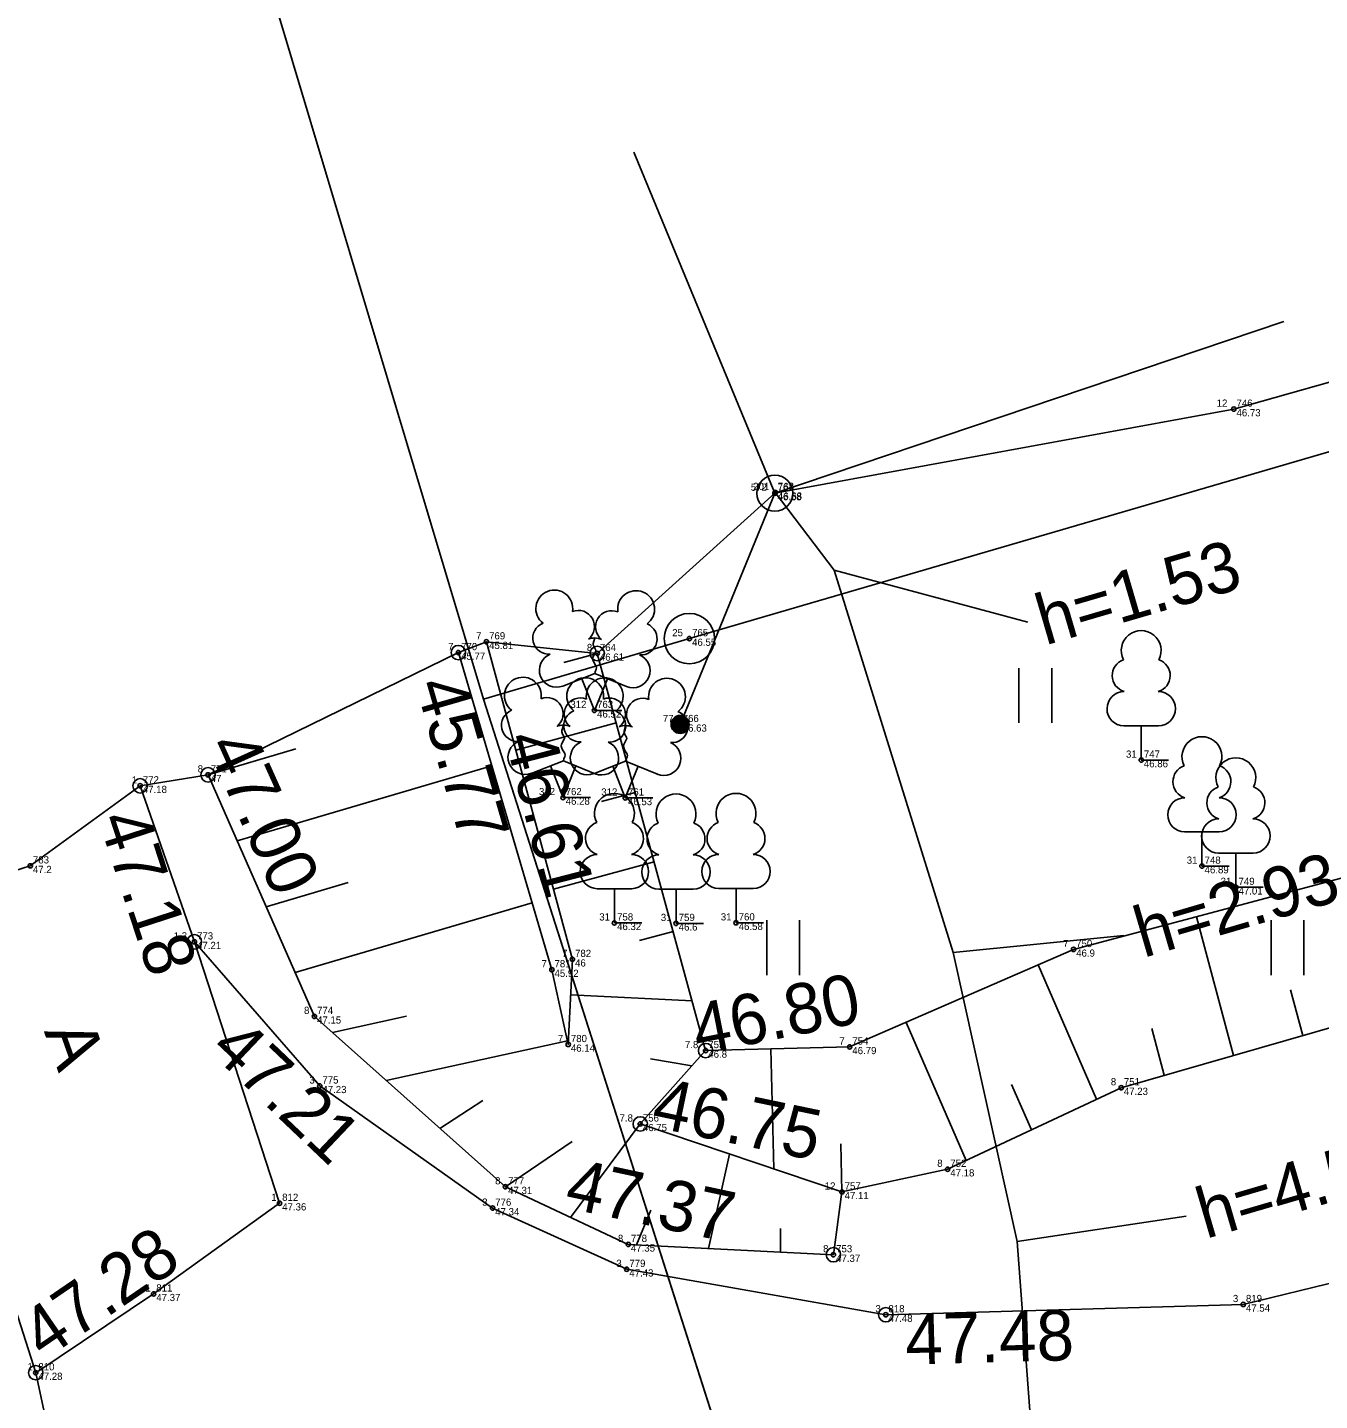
# Model space of a CAD drawing. Extents: x 543497 to 552146, y 6567125 to 6579845.
# Drawn here: x 545912.51 to 545930.45, y 6577662.71 to 6577681.77 of the extents above; entities that cross this region are included whole.
import ezdxf

# ---------------------------------------------------------------- set-up
doc = ezdxf.new("R2010")
doc.units = 0
for name, color, linetype in [('xref_Kangru tee 1_geodeesia$0$ABIJOONIS', 7, 'Continuous'), ('xref_Kangru tee 1_geodeesia$0$HALJASTUS', 7, 'Continuous'), ('xref_Kangru tee 1_geodeesia$0$korgus-EH2000', 7, 'Continuous'), ('xref_Kangru tee 1_geodeesia$0$mootkood', 7, 'Continuous'), ('xref_Kangru tee 1_geodeesia$0$MOOTKORG-eh2000', 7, 'Continuous'), ('xref_Kangru tee 1_geodeesia$0$mootmpunkt', 7, 'Continuous'), ('xref_Kangru tee 1_geodeesia$0$MOOTNR', 7, 'Continuous'), ('xref_Kangru tee 1_geodeesia$0$MOOTPIIR', 7, 'Continuous'), ('xref_Kangru tee 1_geodeesia$0$MPKAABEL', 7, 'Continuous'), ('xref_Kangru tee 1_geodeesia$0$MPOHULIIN', 7, 'Continuous'), ('xref_Kangru tee 1_geodeesia$0$PIIR', 7, 'Continuous'), ('xref_Kangru tee 1_geodeesia$0$PIIRIMLEITUD', 7, 'Continuous'), ('xref_Kangru tee 1_geodeesia$0$Post', 7, 'Continuous'), ('xref_Kangru tee 1_geodeesia$0$PUU', 7, 'Continuous'), ('xref_Kangru tee 1_geodeesia$0$RELJEEF', 7, 'Continuous'), ('xref_Kangru tee 1_geodeesia$0$TEE', 7, 'Continuous')]:
    doc.layers.add(name, color=color, linetype=linetype)

# ---------------------------------------------------------------- blocks, each defined once
blk = doc.blocks.new('xref_Kangru tee 1_geodeesia$0$LEHTP1')
for p, q in [((0.48, 0.95), (-0.48, 0.95)), ((0, 0), (0, 0.95)), ((0.76, 0), (0, 0))]:
    blk.add_line(p, q)
for centre, radius, start, end in [((0, 3.04), 0.554, 332.5799, 207.4201), ((-0.34, 2.345), 0.465, 109.0217, 253.1415), ((0.34, 2.345), 0.465, 286.8508, 70.9859), ((-0.475, 1.425), 0.475, 90.0016, 269.3953), ((0.475, 1.425), 0.475, 270.6047, 89.9984)]:
    blk.add_arc(centre, radius, start, end)
blk = doc.blocks.new('xref_Kangru tee 1_geodeesia$0$LEHTP2')
for p, q in [((-0.88, 0.67), (0.01, 1.02)), ((0, 0), (-0.35, 0.88)), ((0, 0), (0.36, 0.88)), ((0.01, 1.02), (0.89, 0.66)), ((0.76, 0), (0, 0))]:
    blk.add_line(p, q)
blk.add_lwpolyline([(0.01, 2.01), (-0.03, 1.86), (-0.03, 1.82), (-0.01, 1.76), (0.03, 1.69), (0.04, 1.65), (0.01, 1.58), (-0.04, 1.48), (-0.05, 1.43), (-0.04, 1.4), (-0.02, 1.34), (0.05, 1.22), (0.06, 1.18), (0.05, 1.14), (0.02, 1.07), (0.01, 1.02)])
for centre, radius, start, end in [((-1.114, 2.828), 0.512, 111.5027, 232.5173), ((-1.114, 2.828), 0.512, 350.4856, 111.5002), ((1.158, 2.811), 0.512, 67.6168, 188.6314), ((1.158, 2.811), 0.512, 306.5997, 67.6143), ((-0.445, 2.327), 0.448, 308.5041, 111.5725), ((0.481, 2.318), 0.45, 67.7016, 230.5126), ((-1.262, 2.005), 0.448, 111.4304, 274.4987), ((1.293, 1.986), 0.448, 264.6183, 67.6866), ((0.008, 1.535), 0.475, 66.7655, 111.5015), ((-1.053, 1.117), 0.475, 111.5014, 291.5004), ((1.07, 1.101), 0.475, 247.6166, 67.6155)]:
    blk.add_arc(centre, radius, start, end)
blk = doc.blocks.new('xref_Kangru tee 1_geodeesia$0$PMTORU')
blk.add_circle((0, 0), 0.7)
blk = doc.blocks.new('xref_Kangru tee 1_geodeesia$0$PUPOST')
blk.add_circle((0, 0), 0.5)
blk = doc.blocks.new('xref_Kangru tee 1_geodeesia$0$hein')
for p, q in [((-0.455, 0.761), (-0.455, -0.761)), ((0.455, 0.761), (0.455, -0.761))]:
    blk.add_line(p, q)
blk = doc.blocks.new('xref_Kangru tee 1_geodeesia$0$ANKURP')
for radius in [0.25, 0.234, 0.219, 0.203, 0.188, 0.172, 0.156, 0.141, 0.125, 0.11, 0.0939, 0.0783, 0.0628, 0.0472, 0.0316, 0.016, 0.000371]:
    blk.add_circle((0, 0), radius)

msp = doc.modelspace()

# ---------------------------------------------------------------- linework, layer by layer
at = {"layer": 'xref_Kangru tee 1_geodeesia$0$ABIJOONIS'}
for p, q in [((545923.709, 6577674.241), (545926.396, 6577673.517)), ((545925.358, 6577668.93), (545927.728, 6577669.17)), ((545926.248, 6577664.92), (545928.595, 6577665.27))]:
    msp.add_line(p, q, dxfattribs=at)
at = {"layer": 'xref_Kangru tee 1_geodeesia$0$korgus-EH2000'}
for centre in [(545918.49, 6577673.095), (545920.417, 6577673.083), (545914.071, 6577671.246), (545915.014, 6577671.398), (545914.824, 6577669.08), (545921.922, 6577667.571), (545921.014, 6577666.552), (545923.697, 6577664.737), (545924.424, 6577663.904), (545912.621, 6577663.099)]:
    msp.add_circle(centre, 0.1, dxfattribs=at)
at = {"layer": 'xref_Kangru tee 1_geodeesia$0$mootmpunkt'}
for centre in [(545929.256, 6577676.475), (545922.889, 6577675.319), (545922.884, 6577675.308), (545918.879, 6577673.245), (545921.697, 6577673.289), (545918.49, 6577673.095), (545920.417, 6577673.083), (545920.378, 6577672.293), (545921.567, 6577672.098), (545927.97, 6577671.603), (545915.014, 6577671.398), (545914.071, 6577671.246), (545919.942, 6577671.083), (545920.807, 6577671.077), (545912.545, 6577670.135), (545928.813, 6577670.131), (545929.284, 6577669.837), (545920.656, 6577669.343), (545921.511, 6577669.336), (545922.344, 6577669.344), (545914.824, 6577669.08), (545920.072, 6577668.837), (545927.03, 6577668.974), (545919.787, 6577668.693), (545916.49, 6577668.045), (545920.014, 6577667.655), (545921.922, 6577667.571), (545923.922, 6577667.621), (545916.564, 6577667.08), (545927.692, 6577667.055), (545921.014, 6577666.552), (545925.282, 6577665.923), (545919.143, 6577665.68), (545923.815, 6577665.608), (545916.006, 6577665.451), (545918.964, 6577665.384), (545920.848, 6577664.88), (545923.697, 6577664.737), (545920.826, 6577664.534), (545914.258, 6577664.193), (545924.424, 6577663.904), (545929.387, 6577664.046), (545912.621, 6577663.099)]:
    msp.add_circle(centre, 0.03, dxfattribs=at)
at = {"layer": 'xref_Kangru tee 1_geodeesia$0$MOOTPIIR'}
msp.add_lwpolyline([(545946.849, 6577681.441), (545929.256, 6577676.475), (545922.884, 6577675.308), (545920.417, 6577673.083), (545918.879, 6577673.245), (545918.49, 6577673.095), (545915.014, 6577671.398), (545914.071, 6577671.246), (545912.545, 6577670.135), (545910.571, 6577669.508), (545908.59, 6577668.894), (545905.466, 6577667.765), (545904.226, 6577667.219), (545895.757, 6577665.443), (545899.548, 6577655.166)], dxfattribs=at)
at = {"layer": 'xref_Kangru tee 1_geodeesia$0$MPKAABEL'}
msp.add_lwpolyline([(545940.128, 6577606.54), (545939.248, 6577612.58), (545937.798, 6577618.69), (545937.158, 6577621.46), (545934.498, 6577630.73), (545933.268, 6577634.56), (545930.818, 6577642.42), (545930.428, 6577645.32), (545929.638, 6577649.21), (545928.438, 6577653.24), (545926.545, 6577660.97), (545926.248, 6577664.92), (545925.358, 6577668.93), (545923.709, 6577674.241), (545922.889, 6577675.319)], dxfattribs=at)
msp.add_lwpolyline([(545940.128, 6577606.54), (545939.248, 6577612.58), (545937.798, 6577618.69), (545937.158, 6577621.46), (545934.498, 6577630.73), (545933.268, 6577634.56), (545930.818, 6577642.42), (545930.428, 6577645.32), (545929.638, 6577649.21), (545928.438, 6577653.24), (545926.545, 6577660.97), (545926.248, 6577664.92), (545925.358, 6577668.93), (545923.709, 6577674.241), (545922.889, 6577675.319)], dxfattribs=at)
at = {"layer": 'xref_Kangru tee 1_geodeesia$0$MPOHULIIN'}
msp.add_lwpolyline([(545920.925, 6577680.04), (545922.884, 6577675.308), (545929.951, 6577677.692)], dxfattribs=at)
at = {"layer": 'xref_Kangru tee 1_geodeesia$0$PIIR'}
for points in [[(545872.69, 6577782.96), (545871.05, 6577786.39), (545874.7, 6577788.05), (545922.19, 6577809.68), (545973.61, 6577832.94), (545956.36, 6577869.23), (545939.5, 6577905.43), (546028.71, 6577946.4), (546081.11, 6577806.12), (545983.53, 6577775.51), (545969.55, 6577687.28), (545921.7, 6577673.29), (545918.84, 6577672.45), (545911.34, 6577697.47), (545909.71, 6577702.91), (545909.43, 6577705.29), (545905.92, 6577713.46), (545874.41, 6577779.36), (545872.69, 6577782.96)], [(545858.78, 6577811.93), (545870.6, 6577787.32), (545871.05, 6577786.39), (545872.69, 6577782.96), (545874.41, 6577779.36), (545905.92, 6577713.46), (545909.43, 6577705.29), (545909.71, 6577702.91), (545911.34, 6577697.47), (545918.84, 6577672.45), (545925.88, 6577650.4)], [(545526.72, 6577483.94), (545567.61, 6577503.92), (545600.27, 6577519.26), (545639.76, 6577537.43), (545673.8, 6577552.72), (545712.72, 6577569.73), (545743.83, 6577582.87), (545764.02, 6577591.24), (545805.47, 6577607.21), (545907.89, 6577644.25), (545925.88, 6577650.4), (545918.84, 6577672.45), (545921.7, 6577673.29), (545969.55, 6577687.28), (546110.26, 6577728.46), (546113.86, 6577718.6), (546117.94, 6577707.48), (546328.8, 6577761.79)]]:
    msp.add_lwpolyline(points, dxfattribs=at)
at = {"layer": 'xref_Kangru tee 1_geodeesia$0$Post'}
msp.add_line((545922.889, 6577675.319), (545921.567, 6577672.098), dxfattribs=at)
at = {"layer": 'xref_Kangru tee 1_geodeesia$0$RELJEEF'}
for p, q in [((545920.417, 6577673.083), (545919.953, 6577672.957)), ((545920.68, 6577672.118), (545919.286, 6577671.741)), ((545915.014, 6577671.398), (545916.233, 6577671.757)), ((545915.417, 6577670.483), (545918.953, 6577671.525)), ((545920.944, 6577671.154), (545920.478, 6577671.028)), ((545921.207, 6577670.189), (545919.809, 6577669.81)), ((545915.82, 6577669.568), (545916.958, 6577669.903)), ((545916.223, 6577668.652), (545919.513, 6577669.622)), ((545929.251, 6577667.503), (545928.738, 6577669.429)), ((545921.471, 6577669.224), (545921.004, 6577669.098)), ((545927.35, 6577666.894), (545926.538, 6577668.76)), ((545921.734, 6577668.26), (545920.048, 6577668.342)), ((545930.212, 6577667.779), (545930.043, 6577668.415)), ((545916.741, 6577667.821), (545917.771, 6577668.046)), ((545925.539, 6577666.044), (545924.705, 6577667.962)), ((545928.29, 6577667.227), (545928.117, 6577667.875)), ((545917.488, 6577667.156), (545920.003, 6577667.706)), ((545922.867, 6577665.927), (545922.826, 6577667.594)), ((545921.732, 6577667.357), (545921.159, 6577667.457)), ((545926.445, 6577666.469), (545926.17, 6577667.1)), ((545918.234, 6577666.49), (545918.827, 6577666.878)), ((545920.048, 6577665.255), (545921.014, 6577666.552)), ((545919.143, 6577665.68), (545920.069, 6577666.31)), ((545923.815, 6577665.608), (545923.798, 6577666.278)), ((545921.963, 6577664.824), (545922.253, 6577666.134)), ((545920.964, 6577664.874), (545921.16, 6577665.357)), ((545922.962, 6577664.774), (545922.96, 6577665.101))]:
    msp.add_line(p, q, dxfattribs=at)
for points in [[(545919.143, 6577665.68), (545920.848, 6577664.88), (545923.697, 6577664.737), (545923.815, 6577665.608), (545925.282, 6577665.923), (545927.692, 6577667.055), (545947.623, 6577672.78), (545958.409, 6577677.256)], [(545958.409, 6577677.256), (545947.699, 6577674.479), (545927.03, 6577668.974), (545923.922, 6577667.621), (545921.922, 6577667.571)], [(545918.879, 6577673.245), (545920.072, 6577668.837), (545920.014, 6577667.655), (545919.787, 6577668.693), (545918.49, 6577673.095)], [(545920.417, 6577673.083), (545921.922, 6577667.571), (545921.014, 6577666.552)], [(545915.014, 6577671.398), (545916.49, 6577668.045), (545919.143, 6577665.68)], [(545923.815, 6577665.608), (545921.014, 6577666.552)]]:
    msp.add_lwpolyline(points, dxfattribs=at)
at = {"layer": 'xref_Kangru tee 1_geodeesia$0$TEE'}
for points in [[(546059.977, 6577715.174), (546061.866, 6577715.362), (546062.121, 6577710.624), (546061.045, 6577709.272), (546060.882, 6577708.001), (546060.893, 6577706.804), (546060.369, 6577705.849), (546059.158, 6577705.188), (546056.387, 6577704.301), (546050.232, 6577703.156), (546045.314, 6577701.613), (546044.543, 6577701.325), (546040.274, 6577700.368), (546017.855, 6577692.963), (545995.651, 6577685.598), (545969.99, 6577676.752), (545949.859, 6577670.253), (545932.117, 6577664.712), (545929.387, 6577664.046), (545924.424, 6577663.904), (545920.826, 6577664.534), (545918.964, 6577665.384), (545916.564, 6577667.08), (545914.824, 6577669.08)], [(545912.621, 6577663.099), (545913.806, 6577657.552), (545914.534, 6577653.943), (545918.053, 6577653.651), (545920.07, 6577655.546), (545923.655, 6577657.23), (545928.39, 6577658.505), (545934.147, 6577660.131), (545950.841, 6577665.731), (545971.433, 6577672.366), (545997.276, 6577680.49)], [(545910.571, 6577669.508), (545912.621, 6577663.099), (545914.258, 6577664.193), (545916.006, 6577665.451), (545914.824, 6577669.08), (545914.071, 6577671.246)]]:
    msp.add_lwpolyline(points, dxfattribs=at)

# ---------------------------------------------------------------- block references
at = {"layer": 'xref_Kangru tee 1_geodeesia$0$HALJASTUS', "xscale": 0.5, "yscale": 0.5}
for p in [(545926.5, 6577672.5), (545923, 6577669), (545930, 6577669)]:
    msp.add_blockref('xref_Kangru tee 1_geodeesia$0$hein', p, dxfattribs=at)
at = {"layer": 'xref_Kangru tee 1_geodeesia$0$PIIRIMLEITUD', "xscale": 0.5, "yscale": 0.5}
msp.add_blockref('xref_Kangru tee 1_geodeesia$0$PMTORU', (545921.697, 6577673.289), dxfattribs=at)
at = {"layer": 'xref_Kangru tee 1_geodeesia$0$Post', "xscale": 0.5, "yscale": 0.5}
for name, p in [('xref_Kangru tee 1_geodeesia$0$PUPOST', (545922.884, 6577675.308)), ('xref_Kangru tee 1_geodeesia$0$ANKURP', (545921.567, 6577672.098))]:
    msp.add_blockref(name, p, dxfattribs=at)
at = {"layer": 'xref_Kangru tee 1_geodeesia$0$PUU', "xscale": 0.5, "yscale": 0.5}
for name, p in [('xref_Kangru tee 1_geodeesia$0$LEHTP2', (545920.378, 6577672.293)), ('xref_Kangru tee 1_geodeesia$0$LEHTP1', (545927.97, 6577671.603)), ('xref_Kangru tee 1_geodeesia$0$LEHTP2', (545919.942, 6577671.083)), ('xref_Kangru tee 1_geodeesia$0$LEHTP2', (545920.807, 6577671.077)), ('xref_Kangru tee 1_geodeesia$0$LEHTP1', (545928.813, 6577670.131)), ('xref_Kangru tee 1_geodeesia$0$LEHTP1', (545929.284, 6577669.837)), ('xref_Kangru tee 1_geodeesia$0$LEHTP1', (545920.656, 6577669.343)), ('xref_Kangru tee 1_geodeesia$0$LEHTP1', (545921.511, 6577669.336)), ('xref_Kangru tee 1_geodeesia$0$LEHTP1', (545922.344, 6577669.344))]:
    msp.add_blockref(name, p, dxfattribs=at)

# ---------------------------------------------------------------- texts
at = {"layer": 'xref_Kangru tee 1_geodeesia$0$ABIJOONIS'}
for s, rotation, p in [('h=1.53', 16.3152, (545926.635, 6577673.192)), ('h=2.93', 16.3313, (545927.999, 6577668.855)), ('h=4.53', 16.3152, (545928.865, 6577664.954))]:
    msp.add_text(s, height=0.7, rotation=rotation, dxfattribs=at).set_placement(p)
at = {"layer": 'xref_Kangru tee 1_geodeesia$0$korgus-EH2000'}
for s, rotation, p in [(' 45.77 ', 286.0792, (545917.817, 6577672.901)), (' 46.61 ', 284.481, (545919.065, 6577672.165)), (' 47.00 ', 294.2068, (545914.883, 6577672.039)), (' 47.18 ', 288.0001, (545913.405, 6577671.03)), (' 46.80 ', 11.2987, (545921.561, 6577667.459)), (' 47.21 ', 316.4584, (545914.828, 6577667.741)), (' 46.75 ', 348.2294, (545920.894, 6577666.572)), (' 47.37 ', 347.9373, (545919.691, 6577665.45)), (' 47.28 ', 34.4052, (545912.524, 6577663.119)), (' 47.48 ', 1.5466, (545924.443, 6577663.204))]:
    msp.add_text(s, height=0.7, rotation=rotation, dxfattribs=at).set_placement(p)
at = {"layer": 'xref_Kangru tee 1_geodeesia$0$mootkood'}
for s, p in [(' 12', (545928.98, 6577676.508)), (' 572', (545922.513, 6577675.341)), (' 201', (545922.546, 6577675.352)), (' 7', (545918.698, 6577673.278)), (' 25', (545921.421, 6577673.322)), (' 7', (545918.309, 6577673.128)), (' 8', (545920.236, 6577673.116)), (' 312', (545920.007, 6577672.326)), (' 77', (545921.291, 6577672.131)), (' 31', (545927.722, 6577671.636)), (' 8', (545914.833, 6577671.431)), (' 1', (545913.919, 6577671.279)), (' 312', (545919.571, 6577671.116)), (' 312', (545920.436, 6577671.11)), (' 31', (545928.565, 6577670.164)), (' 31', (545929.036, 6577669.87)), (' 31', (545920.408, 6577669.376)), (' 31', (545921.263, 6577669.369)), (' 31', (545922.096, 6577669.377)), (' 1.3', (545914.5, 6577669.113)), (' 7', (545926.849, 6577669.007)), (' 7', (545919.891, 6577668.87)), (' 7', (545919.606, 6577668.726)), (' 8', (545916.309, 6577668.078)), (' 7', (545919.833, 6577667.688)), (' 7', (545923.741, 6577667.654)), (' 7.8', (545921.598, 6577667.604)), (' 3', (545916.383, 6577667.113)), (' 8', (545927.511, 6577667.088)), (' 7.8', (545920.69, 6577666.585)), (' 8', (545925.101, 6577665.956)), (' 8', (545918.962, 6577665.713)), (' 12', (545923.539, 6577665.641)), (' 1', (545915.854, 6577665.484)), (' 3', (545918.783, 6577665.417)), (' 8', (545920.667, 6577664.913)), (' 8', (545923.516, 6577664.77)), (' 3', (545920.645, 6577664.567)), (' 1', (545914.106, 6577664.226)), (' 3', (545929.206, 6577664.079)), (' 3', (545924.243, 6577663.937)), (' 1', (545912.469, 6577663.132))]:
    msp.add_text(s, height=0.1, dxfattribs=at).set_placement(p)
at = {"layer": 'xref_Kangru tee 1_geodeesia$0$MOOTKORG-eh2000'}
for s, p in [(' 46.73', (545929.256, 6577676.375)), (' 46.68', (545922.884, 6577675.208)), (' 46.68', (545922.889, 6577675.219)), (' 46.55', (545921.697, 6577673.189)), (' 45.77', (545918.49, 6577672.995)), (' 45.81', (545918.879, 6577673.145)), (' 46.61', (545920.417, 6577672.983)), (' 46.52', (545920.378, 6577672.193)), (' 46.63', (545921.567, 6577671.998)), (' 46.86', (545927.97, 6577671.503)), (' 47', (545915.014, 6577671.298)), (' 47.18', (545914.071, 6577671.146)), (' 46.28', (545919.942, 6577670.983)), (' 46.53', (545920.807, 6577670.977)), (' 47.2', (545912.545, 6577670.035)), (' 46.89', (545928.813, 6577670.031)), (' 47.01', (545929.284, 6577669.737)), (' 46.32', (545920.656, 6577669.243)), (' 46.6', (545921.511, 6577669.236)), (' 46.58', (545922.344, 6577669.244)), (' 47.21', (545914.824, 6577668.98)), (' 46.9', (545927.03, 6577668.874)), (' 45.92', (545919.787, 6577668.593)), (' 46', (545920.072, 6577668.737)), (' 47.15', (545916.49, 6577667.945)), (' 46.14', (545920.014, 6577667.555)), (' 46.8', (545921.922, 6577667.471)), (' 46.79', (545923.922, 6577667.521)), (' 47.23', (545916.564, 6577666.98)), (' 47.23', (545927.692, 6577666.955)), (' 46.75', (545921.014, 6577666.452)), (' 47.18', (545925.282, 6577665.823)), (' 47.31', (545919.143, 6577665.58)), (' 47.36', (545916.006, 6577665.351)), (' 47.11', (545923.815, 6577665.508)), (' 47.34', (545918.964, 6577665.284)), (' 47.35', (545920.848, 6577664.78)), (' 47.37', (545923.697, 6577664.637)), (' 47.43', (545920.826, 6577664.434)), (' 47.37', (545914.258, 6577664.093)), (' 47.54', (545929.387, 6577663.946)), (' 47.48', (545924.424, 6577663.804)), (' 47.28', (545912.621, 6577662.999))]:
    msp.add_text(s, height=0.1, dxfattribs=at).set_placement(p)
at = {"layer": 'xref_Kangru tee 1_geodeesia$0$MOOTNR'}
for s, p in [(' 746', (545929.256, 6577676.508)), (' 767', (545922.884, 6577675.341)), (' 768', (545922.889, 6577675.352)), (' 769', (545918.879, 6577673.278)), (' 765', (545921.697, 6577673.322)), (' 770', (545918.49, 6577673.128)), (' 764', (545920.417, 6577673.116)), (' 763', (545920.378, 6577672.326)), (' 766', (545921.567, 6577672.131)), (' 747', (545927.97, 6577671.636)), (' 772', (545914.071, 6577671.279)), (' 771', (545915.014, 6577671.431)), (' 762', (545919.942, 6577671.116)), (' 761', (545920.807, 6577671.11)), (' 783', (545912.545, 6577670.168)), (' 748', (545928.813, 6577670.164)), (' 749', (545929.284, 6577669.87)), (' 758', (545920.656, 6577669.376)), (' 759', (545921.511, 6577669.369)), (' 760', (545922.344, 6577669.377)), (' 773', (545914.824, 6577669.113)), (' 750', (545927.03, 6577669.007)), (' 782', (545920.072, 6577668.87)), (' 781', (545919.787, 6577668.726)), (' 774', (545916.49, 6577668.078)), (' 780', (545920.014, 6577667.688)), (' 754', (545923.922, 6577667.654)), (' 755', (545921.922, 6577667.604)), (' 775', (545916.564, 6577667.113)), (' 751', (545927.692, 6577667.088)), (' 756', (545921.014, 6577666.585)), (' 752', (545925.282, 6577665.956)), (' 777', (545919.143, 6577665.713)), (' 757', (545923.815, 6577665.641)), (' 812', (545916.006, 6577665.484)), (' 776', (545918.964, 6577665.417)), (' 778', (545920.848, 6577664.913)), (' 753', (545923.697, 6577664.77)), (' 779', (545920.826, 6577664.567)), (' 811', (545914.258, 6577664.226)), (' 819', (545929.387, 6577664.079)), (' 818', (545924.424, 6577663.937)), (' 810', (545912.621, 6577663.132))]:
    msp.add_text(s, height=0.1, dxfattribs=at).set_placement(p)
at = {"layer": 'xref_Kangru tee 1_geodeesia$0$TEE'}
msp.add_text('A', height=0.7, rotation=289.5227, dxfattribs=at).set_placement((545912.733, 6577667.838))

doc.saveas('drawing.dxf')
